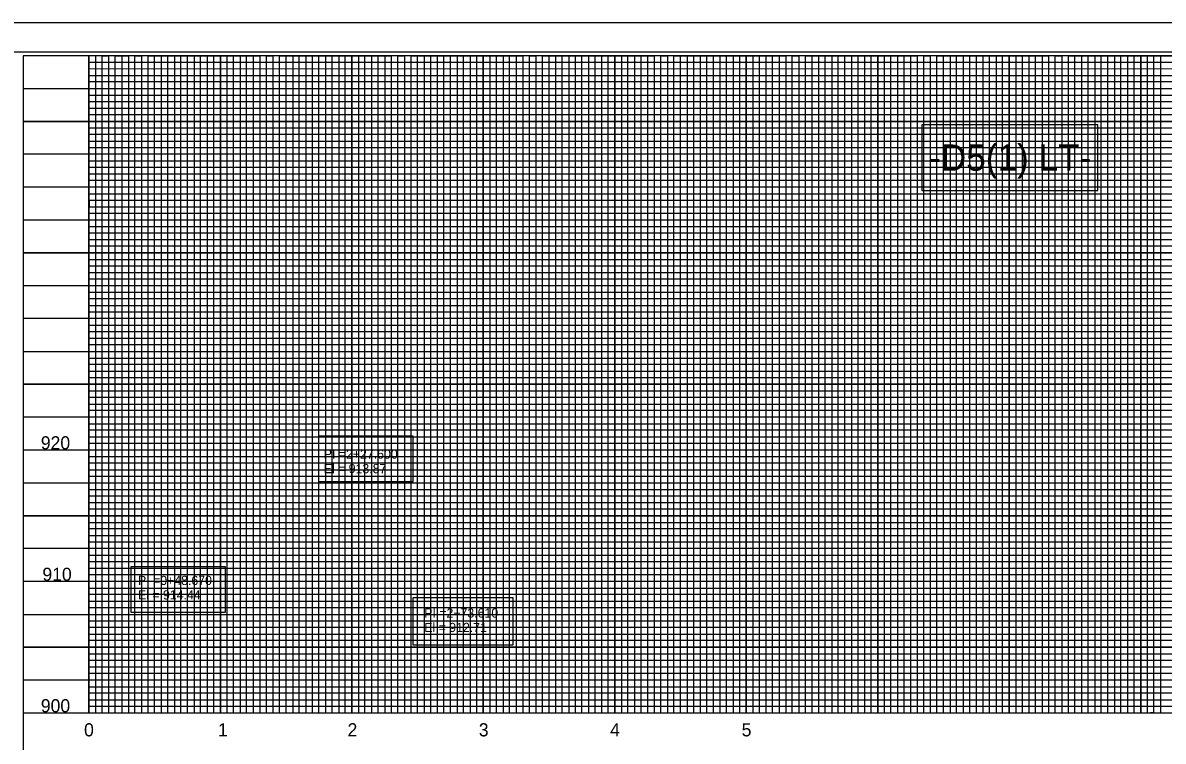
# Model space of a CAD drawing. Extents: x 1647943 to 1651624, y 802691 to 845761.
# Drawn here: x 1649029 to 1649896, y 803245 to 803791 of the extents above; entities that cross this region are included whole.
import ezdxf

# ---------------------------------------------------------------- set-up
doc = ezdxf.new("R2010")
doc.units = 0
for name, color, linetype in [('Exist Vertical Profile Horizontal Axis Label Major', 7, 'Continuous'), ('Exist Vertical Profile Vertical Axis Label', 7, 'Continuous'), ('Prop Grid Mask', 7, 'Continuous'), ('Prop VPI Ditch Grade Left Label', 7, 'Continuous'), ('Sheet Cutting Line CELL', 7, 'Continuous'), ('Sheet DOT Grid CELL', 7, 'Continuous'), ('Sheet Layout Profile Border Port 1', 7, 'Continuous'), ('Sheet Plot Border Inside CELL', 7, 'Continuous'), ('Sheet Plot Border Outside CELL', 7, 'Continuous'), ('Sheet Profile CELL', 7, 'Continuous'), ('Sheet Profile Grid Major CELL', 7, 'Continuous'), ('Sheet Profile Grid Middle CELL', 7, 'Continuous'), ('Sheet Profile Grid Minor CELL', 7, 'Continuous')]:
    doc.layers.add(name, color=color, linetype=linetype)

msp = doc.modelspace()

# ---------------------------------------------------------------- linework, layer by layer
at = {"layer": 'Prop Grid Mask'}
for points in [[(1649712.76, 803713.52), (1649712.76, 803663.52), (1649846.79, 803663.52), (1649846.79, 803713.52)], [(1649712.76, 803713.52), (1649712.76, 803663.52), (1649846.79, 803663.52), (1649846.79, 803713.52)], [(1649253.92, 803476.63), (1649253.92, 803442.22), (1649325.9, 803442.22), (1649325.9, 803476.63)], [(1649111.11, 803377.08), (1649111.11, 803342.67), (1649183.09, 803342.67), (1649183.09, 803377.08)], [(1649325.69, 803353.51), (1649325.69, 803317.73), (1649402.02, 803317.73), (1649402.02, 803353.51)]]:
    msp.add_lwpolyline(points, close=True, dxfattribs=at)
at = {"layer": 'Sheet Cutting Line CELL'}
msp.add_line((1650546.28, 803791.02), (1648862.28, 803791.02), dxfattribs=at)
at = {"layer": 'Sheet DOT Grid CELL'}
for p, q in [((1649079.28, 803266.02), (1649079.28, 803766.02)), ((1649129.28, 803266.02), (1649129.28, 803766.02)), ((1649179.28, 803266.02), (1649179.28, 803766.02)), ((1649229.28, 803266.02), (1649229.28, 803766.02)), ((1649279.28, 803266.02), (1649279.28, 803766.02)), ((1649329.28, 803266.02), (1649329.28, 803766.02)), ((1649379.28, 803266.02), (1649379.28, 803766.02)), ((1649429.28, 803266.02), (1649429.28, 803766.02)), ((1649479.28, 803266.02), (1649479.28, 803766.02)), ((1649529.28, 803266.02), (1649529.28, 803766.02)), ((1649579.28, 803266.02), (1649579.28, 803766.02)), ((1649629.28, 803266.02), (1649629.28, 803766.02)), ((1649679.28, 803266.02), (1649679.28, 803766.02)), ((1649729.28, 803266.02), (1649729.28, 803766.02)), ((1649779.28, 803266.02), (1649779.28, 803766.02)), ((1649829.28, 803266.02), (1649829.28, 803766.02)), ((1649879.28, 803266.02), (1649879.28, 803766.02)), ((1650329.23, 803716.02), (1649029.28, 803716.02)), ((1650329.23, 803666.02), (1649029.28, 803666.02)), ((1650329.28, 803616.02), (1649029.28, 803616.02)), ((1650529.28, 803566.02), (1649029.28, 803566.02)), ((1650529.28, 803516.02), (1649029.28, 803516.02)), ((1650529.28, 803466.02), (1649029.28, 803466.02)), ((1650529.28, 803416.02), (1649029.28, 803416.02)), ((1650529.28, 803366.02), (1649029.28, 803366.02)), ((1650529.28, 803316.02), (1649029.28, 803316.02))]:
    msp.add_line(p, q, dxfattribs=at)
at = {"layer": 'Sheet Layout Profile Border Port 1'}
msp.add_lwpolyline([(1649079.28, 803604.97), (1649079.28, 803266.02), (1650479.28, 803266.02), (1650479.28, 803604.97)], dxfattribs=at)
at = {"layer": 'Sheet Plot Border Inside CELL'}
msp.add_lwpolyline([(1648875.28, 802713.47), (1650541.78, 802713.47), (1650541.78, 803768.57), (1648875.28, 803768.57)], close=True, dxfattribs=at)
at = {"layer": 'Sheet Plot Border Outside CELL'}
msp.add_lwpolyline([(1648862.28, 802691.02), (1650546.28, 802691.02), (1650546.28, 803791.02), (1648862.28, 803791.02)], close=True, dxfattribs=at)
at = {"layer": 'Sheet Profile CELL'}
msp.add_line((1649029.28, 803266.02), (1650529.28, 803266.02), dxfattribs=at)
msp.add_lwpolyline([(1650529.28, 803766.02), (1649029.28, 803766.02), (1649029.28, 802716.02), (1650529.28, 802716.02)], close=True, dxfattribs=at)
at = {"layer": 'Sheet Profile Grid Major CELL'}
for points in [[(1649079.28, 803766.02), (1649079.28, 803266.02), (1649129.28, 803266.02), (1649129.28, 803766.02), (1649179.28, 803766.02), (1649179.28, 803266.02), (1649229.28, 803266.02), (1649229.28, 803766.02), (1649279.28, 803766.02), (1649279.28, 803266.02), (1649329.28, 803266.02), (1649329.28, 803766.02), (1649379.28, 803766.02), (1649379.28, 803266.02), (1649429.28, 803266.02), (1649429.28, 803766.02), (1649479.28, 803766.02), (1649479.28, 803266.02), (1649529.28, 803266.02), (1649529.28, 803766.02), (1649579.28, 803766.02), (1649579.28, 803266.02), (1649629.28, 803266.02), (1649629.28, 803766.02), (1649679.28, 803766.02), (1649679.28, 803266.02), (1649729.28, 803266.02), (1649729.28, 803766.02), (1649779.28, 803766.02), (1649779.28, 803266.02), (1649829.28, 803266.02), (1649829.28, 803766.02), (1649879.28, 803766.02), (1649879.28, 803266.02), (1649929.28, 803266.02)], [(1649029.28, 803716.02), (1650329.28, 803716.02)], [(1650329.28, 803666.02), (1649029.28, 803666.02), (1649029.28, 803616.02), (1650329.28, 803616.02)], [(1650529.28, 803566.02), (1649029.28, 803566.02), (1649029.28, 803516.02), (1650529.28, 803516.02)], [(1650529.28, 803466.02), (1649029.28, 803466.02), (1649029.28, 803416.02), (1650529.28, 803416.02)], [(1650529.28, 803366.02), (1649029.28, 803366.02), (1649029.28, 803366.02), (1649029.28, 803316.02), (1650529.28, 803316.02)]]:
    msp.add_lwpolyline(points, dxfattribs=at)
at = {"layer": 'Sheet Profile Grid Middle CELL'}
msp.add_line((1649029.28, 803741.02), (1650179.28, 803741.02), dxfattribs=at)
for points in [[(1649104.28, 803766.02), (1649104.28, 803266.02), (1649154.28, 803266.02), (1649154.28, 803766.02), (1649204.28, 803766.02), (1649204.28, 803266.02), (1649254.28, 803266.02), (1649254.28, 803766.02), (1649304.28, 803766.02), (1649304.28, 803266.02), (1649354.28, 803266.02), (1649354.28, 803766.02), (1649404.28, 803766.02), (1649404.28, 803266.02), (1649454.28, 803266.02), (1649454.28, 803766.02), (1649504.28, 803766.02), (1649504.28, 803266.02), (1649554.28, 803266.02), (1649554.28, 803766.02), (1649604.28, 803766.02), (1649604.28, 803266.02), (1649654.28, 803266.02), (1649654.28, 803266.02), (1649654.28, 803766.02), (1649704.28, 803766.02), (1649704.28, 803266.02), (1649754.28, 803266.02), (1649754.28, 803766.02), (1649804.28, 803766.02), (1649804.28, 803266.02), (1649854.28, 803266.02), (1649854.28, 803766.02), (1649904.28, 803766.02)], [(1650329.28, 803691.02), (1649029.28, 803691.02), (1649029.28, 803641.02), (1650329.28, 803641.02)], [(1650529.28, 803591.02), (1649029.28, 803591.02), (1649029.28, 803541.02), (1650354.28, 803541.02)], [(1650529.28, 803491.02), (1649029.28, 803491.02), (1649029.28, 803441.02), (1650529.28, 803441.02)], [(1650529.28, 803391.02), (1649029.28, 803391.02), (1649029.28, 803341.02), (1650529.28, 803341.02)], [(1650529.28, 803291.02), (1649029.28, 803291.02)]]:
    msp.add_lwpolyline(points, dxfattribs=at)
at = {"layer": 'Sheet Profile Grid Minor CELL'}
for p, q in [((1649079.28, 803761.02), (1650179.28, 803761.02)), ((1649079.28, 803756.02), (1649079.28, 803756.02)), ((1649079.28, 803756.02), (1649079.28, 803756.02)), ((1649079.28, 803756.02), (1649079.28, 803756.02)), ((1649079.28, 803756.02), (1649079.28, 803756.02)), ((1650179.28, 803755.98), (1649079.28, 803755.67)), ((1649079.28, 803751.02), (1650179.28, 803751.02)), ((1650329.23, 803631.02), (1649079.28, 803631.02)), ((1650329.28, 803626.02), (1649079.28, 803626.02)), ((1650329.28, 803621.02), (1649079.28, 803621.02)), ((1649079.28, 803611.02), (1650329.28, 803611.02)), ((1650329.28, 803606.02), (1649079.28, 803606.02)), ((1649079.28, 803601.02), (1650479.28, 803601.02)), ((1650479.28, 803581.02), (1649079.28, 803581.02)), ((1649079.28, 803576.02), (1650479.28, 803576.02)), ((1650479.28, 803556.02), (1649079.28, 803556.02)), ((1649079.28, 803551.02), (1650479.28, 803551.02)), ((1650479.28, 803531.02), (1649079.28, 803531.02)), ((1649079.28, 803526.02), (1650479.28, 803526.02)), ((1650479.28, 803521.02), (1649079.28, 803521.02)), ((1649079.28, 803511.02), (1650479.28, 803511.02)), ((1650479.28, 803506.02), (1649079.28, 803506.02)), ((1649079.28, 803501.02), (1650479.28, 803501.02)), ((1650479.28, 803496.02), (1649079.28, 803496.02)), ((1649079.28, 803486.02), (1650479.28, 803486.02)), ((1650479.28, 803481.02), (1649079.28, 803481.02)), ((1649079.28, 803476.02), (1650479.28, 803476.02)), ((1650479.28, 803471.02), (1649079.28, 803471.02)), ((1649079.28, 803461.02), (1650479.28, 803461.02)), ((1650479.28, 803456.02), (1649079.28, 803456.02)), ((1649079.28, 803451.02), (1650479.28, 803451.02)), ((1650479.28, 803446.02), (1649079.28, 803446.02)), ((1649079.28, 803436.02), (1650479.28, 803436.02)), ((1650479.28, 803431.02), (1649079.28, 803431.02)), ((1649079.28, 803426.02), (1650479.28, 803426.02)), ((1650479.28, 803421.02), (1649079.28, 803421.02)), ((1649079.28, 803411.02), (1650479.28, 803411.02)), ((1650479.28, 803406.02), (1649079.28, 803406.02)), ((1649079.28, 803401.02), (1650479.28, 803401.02)), ((1650479.28, 803396.02), (1649079.28, 803396.02)), ((1649079.28, 803386.02), (1650479.28, 803386.02)), ((1650479.28, 803381.02), (1649079.28, 803381.02)), ((1650479.28, 803376.02), (1649079.28, 803376.02)), ((1650479.28, 803371.02), (1649079.28, 803371.02)), ((1649079.28, 803361.02), (1650479.28, 803361.02)), ((1650479.28, 803356.02), (1649079.28, 803356.02)), ((1649079.28, 803351.02), (1650479.28, 803351.02)), ((1650479.28, 803346.02), (1649079.28, 803346.02)), ((1649079.28, 803336.02), (1650479.28, 803336.02)), ((1650479.28, 803331.02), (1649079.28, 803331.02)), ((1649079.28, 803326.02), (1650479.28, 803326.02)), ((1650479.28, 803321.02), (1649079.28, 803321.02)), ((1649079.28, 803311.02), (1650479.28, 803311.02)), ((1650479.28, 803306.02), (1649079.28, 803306.02)), ((1649079.28, 803301.02), (1650479.28, 803301.02)), ((1650479.28, 803296.02), (1649079.28, 803296.02)), ((1649079.28, 803286.02), (1650479.28, 803286.02)), ((1650479.28, 803281.02), (1649079.28, 803281.02)), ((1649079.28, 803276.02), (1650479.28, 803276.02))]:
    msp.add_line(p, q, dxfattribs=at)
for points in [[(1649084.28, 803766.02), (1649084.28, 803266.02), (1649089.28, 803266.02), (1649089.28, 803766.02), (1649094.28, 803766.02), (1649094.28, 803266.02), (1649099.28, 803266.02), (1649099.28, 803766.02), (1649109.28, 803766.02), (1649109.28, 803266.02), (1649114.28, 803266.02), (1649114.28, 803766.02), (1649119.28, 803766.02), (1649119.28, 803266.02), (1649124.28, 803266.02), (1649134.28, 803266.02), (1649139.28, 803266.02), (1649139.28, 803766.02), (1649144.28, 803766.02), (1649144.28, 803266.02), (1649149.28, 803266.02), (1649149.28, 803766.02), (1649159.28, 803766.02), (1649159.28, 803266.02), (1649164.28, 803266.02), (1649164.28, 803766.02), (1649169.28, 803766.02), (1649169.28, 803266.02), (1649174.28, 803266.02), (1649174.28, 803766.02), (1649184.28, 803766.02), (1649184.28, 803266.02), (1649189.28, 803266.02), (1649189.28, 803766.02), (1649194.28, 803766.02), (1649194.28, 803266.02), (1649199.28, 803266.02), (1649199.28, 803766.02), (1649209.28, 803766.02), (1649209.28, 803266.02), (1649214.28, 803266.02), (1649214.28, 803766.02), (1649219.28, 803766.02), (1649219.28, 803266.02), (1649224.28, 803266.02), (1649224.28, 803766.02), (1649234.28, 803766.02), (1649234.28, 803266.02), (1649239.28, 803266.02), (1649239.28, 803766.02), (1649244.28, 803766.02), (1649244.28, 803266.02), (1649249.28, 803266.02), (1649249.28, 803766.02), (1649259.28, 803766.02), (1649259.28, 803266.02), (1649264.28, 803266.02), (1649264.28, 803766.02), (1649269.28, 803766.02), (1649269.28, 803266.02), (1649274.28, 803266.02), (1649274.28, 803766.02), (1649284.28, 803766.02), (1649284.28, 803266.02), (1649289.28, 803266.02), (1649289.28, 803766.02), (1649294.28, 803766.02), (1649294.28, 803266.02)], [(1649124.28, 803266.02), (1649124.28, 803766.02), (1649134.28, 803766.02), (1649134.28, 803266.02)], [(1649294.28, 803266.02), (1649299.28, 803266.02), (1649299.28, 803766.02), (1649309.28, 803766.02), (1649309.28, 803266.02), (1649314.28, 803266.02), (1649314.28, 803766.02), (1649319.28, 803766.02), (1649319.28, 803266.02), (1649324.28, 803266.02), (1649324.28, 803766.02), (1649334.28, 803766.02), (1649334.28, 803266.02), (1649339.28, 803266.02), (1649339.28, 803766.02), (1649344.28, 803766.02), (1649344.28, 803266.02), (1649349.28, 803266.02), (1649349.28, 803766.02), (1649359.28, 803766.02), (1649359.28, 803266.02), (1649364.28, 803266.02), (1649364.28, 803766.02), (1649369.28, 803766.02), (1649369.28, 803266.02), (1649374.28, 803266.02), (1649374.28, 803766.02), (1649384.28, 803766.02), (1649384.28, 803266.02), (1649389.28, 803266.02), (1649389.28, 803766.02), (1649394.28, 803766.02), (1649394.28, 803266.02), (1649399.28, 803266.02), (1649399.28, 803766.02), (1649409.28, 803766.02), (1649409.28, 803266.02), (1649414.28, 803266.02), (1649414.28, 803766.02), (1649419.28, 803766.02), (1649419.28, 803266.02), (1649424.28, 803266.02), (1649424.28, 803766.02), (1649434.28, 803766.02), (1649434.28, 803266.02), (1649439.28, 803266.02), (1649439.28, 803766.02), (1649444.28, 803766.02), (1649444.28, 803266.02), (1649449.28, 803266.02), (1649449.28, 803766.02), (1649459.28, 803766.02), (1649459.28, 803266.02), (1649464.28, 803266.02), (1649464.28, 803766.02), (1649469.28, 803766.02), (1649469.28, 803266.02), (1649474.28, 803266.02), (1649474.28, 803766.02), (1649484.28, 803766.02), (1649484.28, 803266.02), (1649489.28, 803266.02), (1649489.28, 803766.02), (1649494.28, 803766.02), (1649494.28, 803266.02), (1649499.28, 803266.02), (1649499.28, 803766.02), (1649509.28, 803766.02), (1649509.28, 803266.02), (1649514.28, 803266.02), (1649514.28, 803766.02), (1649519.28, 803766.02), (1649519.28, 803266.02), (1649524.28, 803266.02), (1649524.28, 803766.02), (1649534.28, 803766.02), (1649534.28, 803266.02), (1649539.28, 803266.02), (1649539.28, 803766.02), (1649544.28, 803766.02), (1649544.28, 803266.02), (1649549.28, 803266.02), (1649549.28, 803766.02), (1649559.28, 803766.02), (1649559.28, 803266.02), (1649564.28, 803266.02), (1649564.28, 803766.02), (1649569.28, 803766.02), (1649569.28, 803266.02), (1649574.28, 803266.02), (1649574.28, 803766.02), (1649584.28, 803766.02), (1649584.28, 803266.02), (1649589.28, 803266.02), (1649589.28, 803766.02), (1649594.28, 803766.02), (1649594.28, 803266.02), (1649599.28, 803266.02), (1649599.28, 803766.02), (1649609.28, 803766.02)], [(1649609.28, 803766.02), (1649609.28, 803266.02), (1649614.28, 803266.02), (1649614.28, 803766.02), (1649619.28, 803766.02), (1649619.28, 803266.02), (1649624.28, 803266.02), (1649624.28, 803766.02), (1649634.28, 803766.02), (1649634.28, 803266.02), (1649639.28, 803266.02), (1649639.28, 803766.02), (1649644.28, 803766.02), (1649644.28, 803266.02), (1649649.28, 803266.02), (1649649.28, 803766.02), (1649659.28, 803766.02), (1649659.28, 803266.02), (1649664.28, 803266.02), (1649664.28, 803766.02), (1649669.28, 803766.02), (1649669.28, 803266.02), (1649674.28, 803266.02), (1649674.28, 803766.02), (1649684.28, 803766.02), (1649684.28, 803266.02), (1649689.28, 803266.02), (1649689.28, 803766.02), (1649694.28, 803766.02), (1649694.28, 803266.02), (1649699.28, 803266.02), (1649699.28, 803766.02), (1649709.28, 803766.02), (1649709.28, 803266.02), (1649714.28, 803266.02), (1649714.28, 803766.02), (1649719.28, 803766.02), (1649719.28, 803266.02), (1649724.28, 803266.02), (1649724.28, 803766.02), (1649734.28, 803766.02), (1649734.28, 803266.02), (1649734.28, 803266.02), (1649739.28, 803266.02), (1649739.28, 803766.02), (1649744.28, 803766.02), (1649744.28, 803266.02), (1649749.28, 803266.02), (1649749.28, 803766.02), (1649759.28, 803766.02), (1649759.28, 803266.02), (1649764.28, 803266.02), (1649764.28, 803766.02), (1649769.28, 803766.02), (1649769.28, 803266.02), (1649774.28, 803266.02), (1649774.28, 803766.02), (1649784.28, 803766.02), (1649784.28, 803266.02), (1649789.28, 803266.02), (1649789.28, 803766.02), (1649794.28, 803766.02), (1649794.28, 803266.02), (1649799.28, 803266.02), (1649799.28, 803766.02), (1649809.28, 803766.02), (1649809.28, 803266.02), (1649814.28, 803266.02), (1649814.28, 803766.02), (1649819.28, 803766.02), (1649819.28, 803266.02), (1649824.28, 803266.02), (1649824.28, 803766.02), (1649834.28, 803766.02), (1649834.28, 803266.02), (1649839.28, 803266.02), (1649839.28, 803766.02), (1649844.28, 803766.02), (1649844.28, 803266.02), (1649849.28, 803266.02), (1649849.28, 803766.02), (1649859.28, 803766.02), (1649859.28, 803266.02), (1649864.28, 803266.02), (1649864.28, 803766.02), (1649869.28, 803766.02), (1649869.28, 803266.02), (1649874.28, 803266.02), (1649874.28, 803766.02), (1649884.28, 803766.02), (1649884.28, 803266.02), (1649888.98, 803266.57), (1649889.28, 803266.02), (1649889.28, 803766.02), (1649894.28, 803766.02), (1649894.28, 803266.02), (1649899.28, 803266.02)], [(1650179.28, 803746.02), (1649079.28, 803746.02), (1649079.28, 803736.02), (1650329.28, 803736.02)], [(1650329.23, 803731.02), (1649079.28, 803731.02), (1649079.28, 803726.02), (1650329.28, 803726.02)], [(1650329.28, 803721.02), (1649079.28, 803721.02), (1649079.28, 803711.02), (1650329.28, 803711.02)], [(1650329.28, 803706.02), (1649079.28, 803706.02), (1649079.28, 803701.02), (1650329.28, 803701.02)], [(1650329.28, 803696.02), (1649079.28, 803696.02), (1649079.28, 803686.02), (1650329.28, 803686.02)], [(1650329.28, 803681.02), (1649079.28, 803681.02), (1649079.28, 803676.02), (1650329.28, 803676.02)], [(1650329.28, 803671.02), (1649079.28, 803671.02), (1649079.28, 803661.02), (1650329.28, 803661.02)], [(1650329.28, 803655.92), (1649079.38, 803655.92), (1649079.38, 803651.02), (1650329.28, 803651.02)], [(1650329.28, 803646.02), (1649079.28, 803646.02), (1649079.28, 803636.02), (1650329.28, 803636.02)], [(1650479.28, 803596.02), (1649079.28, 803596.02), (1649079.28, 803586.02), (1650479.28, 803586.02)], [(1650479.28, 803571.02), (1649079.28, 803571.02), (1649079.28, 803561.02), (1650479.28, 803561.02)], [(1650479.28, 803546.02), (1649079.28, 803546.02), (1649079.28, 803536.02), (1650479.28, 803536.02)], [(1650479.28, 803271.02), (1649079.28, 803271.02)]]:
    msp.add_lwpolyline(points, dxfattribs=at)

# ---------------------------------------------------------------- texts
at = {"layer": 'Exist Vertical Profile Horizontal Axis Label Major'}
for s, height, p in [('-D5(1) LT-', 20, (1649718.36, 803678.52)), ('-D5(1) LT-', 20, (1649718.36, 803678.52)), ('0', 10, (1649075.62, 803248.21)), ('1', 10, (1649177.46, 803248.21)), ('2', 10, (1649276.01, 803248.21)), ('3', 10, (1649375.85, 803248.21)), ('4', 10, (1649475.69, 803248.21)), ('5', 10, (1649575.78, 803248.21))]:
    msp.add_text(s, height=height, dxfattribs=at).set_placement(p)
at = {"layer": 'Exist Vertical Profile Vertical Axis Label'}
for s, p in [('920', (1649042.71, 803466.52)), ('910', (1649043.91, 803366.52)), ('900', (1649042.71, 803266.52))]:
    msp.add_text(s, height=10, dxfattribs=at).set_placement(p)
at = {"layer": 'Prop VPI Ditch Grade Left Label'}
for s, p in [('PI =2+27.600', (1649257.92, 803459.43)), ('El = 913.87', (1649257.92, 803448.43)), ('PI =0+48.670', (1649116.65, 803363.35)), ('El = 914.44', (1649116.65, 803352.35)), ('PI =2+73.610', (1649334.37, 803338.57)), ('El = 912.71', (1649334.37, 803327.57))]:
    msp.add_text(s, height=7, dxfattribs=at).set_placement(p)

doc.saveas('drawing.dxf')
